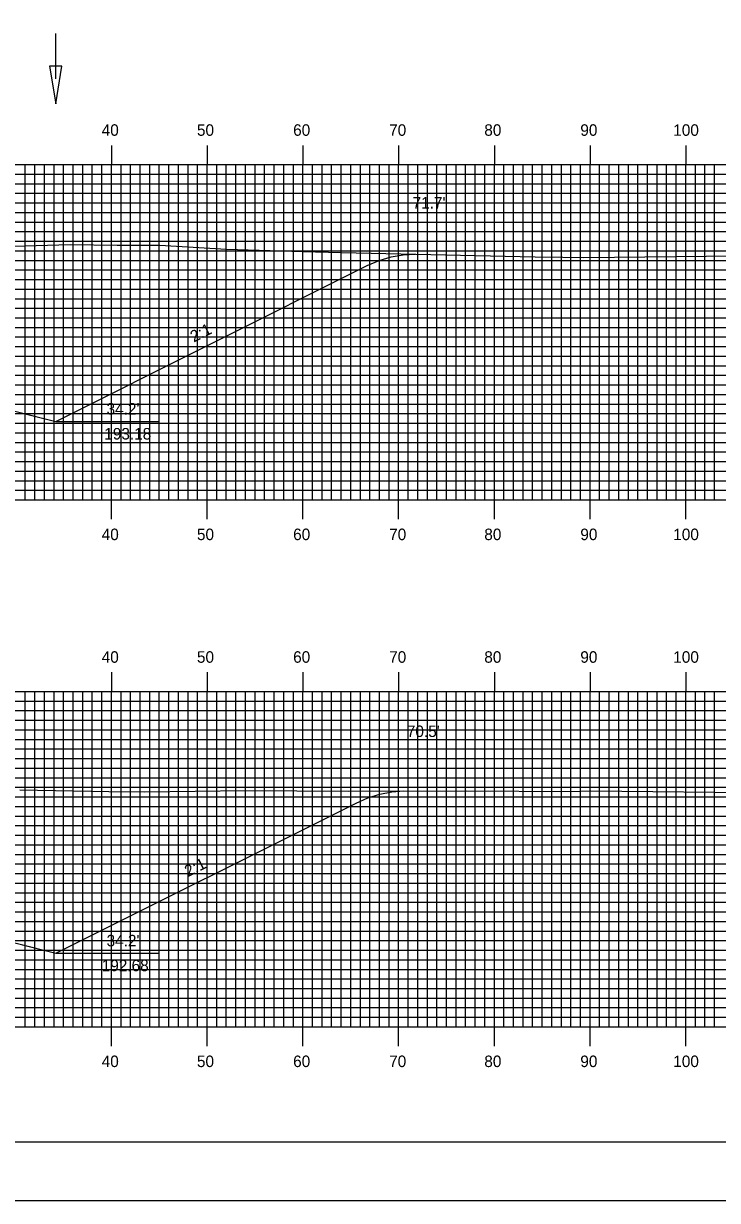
# Model space of a CAD drawing. Extents: x 1799962 to 1800305, y 442591 to 442811.
# Drawn here: x 1800158.3 to 1800230.8, y 442590.5 to 442713.4 of the extents above; entities that cross this region are included whole.
import ezdxf

# ---------------------------------------------------------------- set-up
doc = ezdxf.new("R2010")
doc.units = 0
for name, color, linetype in [('ANNOTATION', 7, 'Continuous'), ('BORDER', 7, 'Continuous'), ('D_Drainage_Ditch_Line', 7, 'Continuous'), ('D_Roadway_Centerline', 7, 'Continuous'), ('D_Roadway_SlopeLines', 7, 'Continuous'), ('D_Text_Standard', 7, 'Continuous'), ('H_V ANNOTATION', 7, 'Continuous'), ('MAJOR', 7, 'Continuous'), ('MINOR', 7, 'Continuous'), ('PDRAIN', 7, 'Continuous'), ('PLOT BOUNDARY', 7, 'Continuous'), ('S_Roadway_Centerline', 7, 'Continuous')]:
    doc.layers.add(name, color=color, linetype=linetype)

msp = doc.modelspace()

# ---------------------------------------------------------------- linework, layer by layer
at = {"layer": 'BORDER'}
msp.add_lwpolyline([(1799977.92, 442596.67), (1800297.92, 442596.67), (1800297.92, 442806.67), (1799977.92, 442806.67)], close=True, dxfattribs=at)
at = {"layer": 'D_Drainage_Ditch_Line'}
msp.add_line((1800161.7, 442707.63), (1800161.7, 442712.33), dxfattribs=at)
msp.add_lwpolyline([(1800162.35, 442708.94), (1800161.04, 442708.94), (1800161.7, 442705)], close=True, dxfattribs=at)
at = {"layer": 'D_Roadway_Centerline'}
for points in [[(1800054.75, 442690.37), (1800056, 442690.29), (1800057.25, 442690.06), (1800058.5, 442689.67), (1800059.75, 442689.13), (1800093.35, 442672.33), (1800097.35, 442673.33), (1800107.52, 442675.87), (1800115.52, 442676.19), (1800127.52, 442675.95), (1800139.52, 442675.71), (1800147.52, 442675.39), (1800157.7, 442672.85), (1800161.7, 442671.85), (1800194.25, 442688.12), (1800195.5, 442688.67), (1800196.75, 442689.05), (1800198, 442689.26), (1800199.25, 442689.32)], [(1800057.29, 442633.58), (1800058.54, 442633.51), (1800059.79, 442633.29), (1800061.04, 442632.9), (1800062.29, 442632.35), (1800093.35, 442616.83), (1800097.35, 442617.83), (1800107.52, 442620.37), (1800115.52, 442620.69), (1800127.52, 442620.45), (1800139.52, 442620.21), (1800147.52, 442619.89), (1800157.7, 442617.35), (1800161.7, 442616.35), (1800193.07, 442632.03), (1800194.32, 442632.58), (1800195.57, 442632.97), (1800196.82, 442633.21), (1800198.07, 442633.29)]]:
    msp.add_lwpolyline(points, dxfattribs=at)
at = {"layer": 'D_Roadway_SlopeLines'}
for points in [[(1800161.7, 442671.85), (1800194.25, 442688.12), (1800195.5, 442688.67), (1800196.75, 442689.05), (1800198, 442689.26), (1800199.25, 442689.32)], [(1800147.52, 442675.39), (1800161.7, 442671.85)], [(1800161.7, 442616.35), (1800193.07, 442632.03), (1800194.32, 442632.58), (1800195.57, 442632.97), (1800196.82, 442633.21), (1800198.07, 442633.29)], [(1800147.52, 442619.89), (1800161.7, 442616.35)]]:
    msp.add_lwpolyline(points, dxfattribs=at)
at = {"layer": 'MAJOR'}
for p, q in [((1800167.52, 442700.67), (1800167.52, 442698.67)), ((1800177.52, 442700.67), (1800177.52, 442698.67)), ((1800187.52, 442700.67), (1800187.52, 442698.67)), ((1800197.52, 442700.67), (1800197.52, 442698.67)), ((1800207.52, 442700.67), (1800207.52, 442698.67)), ((1800217.52, 442700.67), (1800217.52, 442698.67)), ((1800227.52, 442700.67), (1800227.52, 442698.67)), ((1799987.52, 442698.67), (1800267.52, 442698.67)), ((1799987.52, 442698.67), (1800267.52, 442698.67)), ((1800167.52, 442663.67), (1800167.52, 442698.67)), ((1800177.52, 442663.67), (1800177.52, 442698.67)), ((1800187.52, 442663.67), (1800187.52, 442698.67)), ((1800197.52, 442663.67), (1800197.52, 442698.67)), ((1800207.52, 442663.67), (1800207.52, 442698.67)), ((1800217.52, 442663.67), (1800217.52, 442698.67)), ((1800227.52, 442663.67), (1800227.52, 442698.67)), ((1799987.52, 442693.67), (1800267.52, 442693.67)), ((1799987.52, 442688.67), (1800267.52, 442688.67)), ((1799987.52, 442683.67), (1800267.52, 442683.67)), ((1799987.52, 442678.67), (1800267.52, 442678.67)), ((1799987.52, 442673.67), (1800267.52, 442673.67)), ((1799987.52, 442668.67), (1800267.52, 442668.67)), ((1799987.52, 442663.67), (1800267.52, 442663.67)), ((1799987.52, 442663.67), (1800267.52, 442663.67)), ((1800167.52, 442661.66), (1800167.52, 442663.67)), ((1800177.52, 442661.66), (1800177.52, 442663.67)), ((1800187.52, 442661.66), (1800187.52, 442663.67)), ((1800197.52, 442661.66), (1800197.52, 442663.67)), ((1800207.52, 442661.66), (1800207.52, 442663.67)), ((1800217.52, 442661.66), (1800217.52, 442663.67)), ((1800227.52, 442661.66), (1800227.52, 442663.67)), ((1800167.52, 442645.67), (1800167.52, 442643.67)), ((1800177.52, 442645.67), (1800177.52, 442643.67)), ((1800187.52, 442645.67), (1800187.52, 442643.67)), ((1800197.52, 442645.67), (1800197.52, 442643.67)), ((1800207.52, 442645.67), (1800207.52, 442643.67)), ((1800217.52, 442645.67), (1800217.52, 442643.67)), ((1800227.52, 442645.67), (1800227.52, 442643.67)), ((1799987.52, 442643.67), (1800267.52, 442643.67)), ((1799987.52, 442643.67), (1800267.52, 442643.67)), ((1800167.52, 442608.67), (1800167.52, 442643.67)), ((1800177.52, 442608.67), (1800177.52, 442643.67)), ((1800187.52, 442608.67), (1800187.52, 442643.67)), ((1800197.52, 442608.67), (1800197.52, 442643.67)), ((1800207.52, 442608.67), (1800207.52, 442643.67)), ((1800217.52, 442608.67), (1800217.52, 442643.67)), ((1800227.52, 442608.67), (1800227.52, 442643.67)), ((1799987.52, 442638.67), (1800267.52, 442638.67)), ((1799987.52, 442633.67), (1800267.52, 442633.67)), ((1799987.52, 442628.67), (1800267.52, 442628.67)), ((1799987.52, 442623.67), (1800267.52, 442623.67)), ((1799987.52, 442618.67), (1800267.52, 442618.67)), ((1799987.52, 442613.67), (1800267.52, 442613.67)), ((1799987.52, 442608.67), (1800267.52, 442608.67)), ((1799987.52, 442608.67), (1800267.52, 442608.67)), ((1800167.52, 442606.66), (1800167.52, 442608.67)), ((1800177.52, 442606.66), (1800177.52, 442608.67)), ((1800187.52, 442606.66), (1800187.52, 442608.67)), ((1800197.52, 442606.66), (1800197.52, 442608.67)), ((1800207.52, 442606.66), (1800207.52, 442608.67)), ((1800217.52, 442606.66), (1800217.52, 442608.67)), ((1800227.52, 442606.66), (1800227.52, 442608.67))]:
    msp.add_line(p, q, dxfattribs=at)
at = {"layer": 'MINOR'}
for p, q in [((1800158.52, 442663.67), (1800158.52, 442698.67)), ((1800159.52, 442663.67), (1800159.52, 442698.67)), ((1800160.52, 442663.67), (1800160.52, 442698.67)), ((1800161.52, 442663.67), (1800161.52, 442698.67)), ((1800162.52, 442663.67), (1800162.52, 442698.67)), ((1800163.52, 442663.67), (1800163.52, 442698.67)), ((1800164.52, 442663.67), (1800164.52, 442698.67)), ((1800165.52, 442663.67), (1800165.52, 442698.67)), ((1800166.52, 442663.67), (1800166.52, 442698.67)), ((1800168.52, 442663.67), (1800168.52, 442698.67)), ((1800169.52, 442663.67), (1800169.52, 442698.67)), ((1800170.52, 442663.67), (1800170.52, 442698.67)), ((1800171.52, 442663.67), (1800171.52, 442698.67)), ((1800172.52, 442663.67), (1800172.52, 442698.67)), ((1800173.52, 442663.67), (1800173.52, 442698.67)), ((1800174.52, 442663.67), (1800174.52, 442698.67)), ((1800175.52, 442663.67), (1800175.52, 442698.67)), ((1800176.52, 442663.67), (1800176.52, 442698.67)), ((1800178.52, 442663.67), (1800178.52, 442698.67)), ((1800179.52, 442663.67), (1800179.52, 442698.67)), ((1800180.52, 442663.67), (1800180.52, 442698.67)), ((1800181.52, 442663.67), (1800181.52, 442698.67)), ((1800182.52, 442663.67), (1800182.52, 442698.67)), ((1800183.52, 442663.67), (1800183.52, 442698.67)), ((1800184.52, 442663.67), (1800184.52, 442698.67)), ((1800185.52, 442663.67), (1800185.52, 442698.67)), ((1800186.52, 442663.67), (1800186.52, 442698.67)), ((1800188.52, 442663.67), (1800188.52, 442698.67)), ((1800189.52, 442663.67), (1800189.52, 442698.67)), ((1800190.52, 442663.67), (1800190.52, 442698.67)), ((1800191.52, 442663.67), (1800191.52, 442698.67)), ((1800192.52, 442663.67), (1800192.52, 442698.67)), ((1800193.52, 442663.67), (1800193.52, 442698.67)), ((1800194.52, 442663.67), (1800194.52, 442698.67)), ((1800195.52, 442663.67), (1800195.52, 442698.67)), ((1800196.52, 442663.67), (1800196.52, 442698.67)), ((1800198.52, 442663.67), (1800198.52, 442698.67)), ((1800199.52, 442663.67), (1800199.52, 442698.67)), ((1800200.52, 442663.67), (1800200.52, 442698.67)), ((1800201.52, 442663.67), (1800201.52, 442698.67)), ((1800202.52, 442663.67), (1800202.52, 442698.67)), ((1800203.52, 442663.67), (1800203.52, 442698.67)), ((1800204.52, 442663.67), (1800204.52, 442698.67)), ((1800205.52, 442663.67), (1800205.52, 442698.67)), ((1800206.52, 442663.67), (1800206.52, 442698.67)), ((1800208.52, 442663.67), (1800208.52, 442698.67)), ((1800209.52, 442663.67), (1800209.52, 442698.67)), ((1800210.52, 442663.67), (1800210.52, 442698.67)), ((1800211.52, 442663.67), (1800211.52, 442698.67)), ((1800212.52, 442663.67), (1800212.52, 442698.67)), ((1800213.52, 442663.67), (1800213.52, 442698.67)), ((1800214.52, 442663.67), (1800214.52, 442698.67)), ((1800215.52, 442663.67), (1800215.52, 442698.67)), ((1800216.52, 442663.67), (1800216.52, 442698.67)), ((1800218.52, 442663.67), (1800218.52, 442698.67)), ((1800219.52, 442663.67), (1800219.52, 442698.67)), ((1800220.52, 442663.67), (1800220.52, 442698.67)), ((1800221.52, 442663.67), (1800221.52, 442698.67)), ((1800222.52, 442663.67), (1800222.52, 442698.67)), ((1800223.52, 442663.67), (1800223.52, 442698.67)), ((1800224.52, 442663.67), (1800224.52, 442698.67)), ((1800225.52, 442663.67), (1800225.52, 442698.67)), ((1800226.52, 442663.67), (1800226.52, 442698.67)), ((1800228.52, 442663.67), (1800228.52, 442698.67)), ((1800229.52, 442663.67), (1800229.52, 442698.67)), ((1800230.52, 442663.67), (1800230.52, 442698.67)), ((1799987.52, 442697.67), (1800267.52, 442697.67)), ((1799987.52, 442696.67), (1800267.52, 442696.67)), ((1799987.52, 442695.67), (1800267.52, 442695.67)), ((1799987.52, 442694.67), (1800267.52, 442694.67)), ((1799987.52, 442692.67), (1800267.52, 442692.67)), ((1799987.52, 442691.67), (1800267.52, 442691.67)), ((1799987.52, 442690.67), (1800267.52, 442690.67)), ((1799987.52, 442689.67), (1800267.52, 442689.67)), ((1799987.52, 442687.67), (1800267.52, 442687.67)), ((1799987.52, 442686.67), (1800267.52, 442686.67)), ((1799987.52, 442685.67), (1800267.52, 442685.67)), ((1799987.52, 442684.67), (1800267.52, 442684.67)), ((1799987.52, 442682.67), (1800267.52, 442682.67)), ((1799987.52, 442681.67), (1800267.52, 442681.67)), ((1799987.52, 442680.67), (1800267.52, 442680.67)), ((1799987.52, 442679.67), (1800267.52, 442679.67)), ((1799987.52, 442677.67), (1800267.52, 442677.67)), ((1799987.52, 442676.67), (1800267.52, 442676.67)), ((1799987.52, 442675.67), (1800267.52, 442675.67)), ((1799987.52, 442674.67), (1800267.52, 442674.67)), ((1799987.52, 442672.67), (1800267.52, 442672.67)), ((1799987.52, 442671.67), (1800267.52, 442671.67)), ((1799987.52, 442670.67), (1800267.52, 442670.67)), ((1799987.52, 442669.67), (1800267.52, 442669.67)), ((1799987.52, 442667.67), (1800267.52, 442667.67)), ((1799987.52, 442666.67), (1800267.52, 442666.67)), ((1799987.52, 442665.67), (1800267.52, 442665.67)), ((1799987.52, 442664.67), (1800267.52, 442664.67)), ((1800158.52, 442608.67), (1800158.52, 442643.67)), ((1800159.52, 442608.67), (1800159.52, 442643.67)), ((1800160.52, 442608.67), (1800160.52, 442643.67)), ((1800161.52, 442608.67), (1800161.52, 442643.67)), ((1800162.52, 442608.67), (1800162.52, 442643.67)), ((1800163.52, 442608.67), (1800163.52, 442643.67)), ((1800164.52, 442608.67), (1800164.52, 442643.67)), ((1800165.52, 442608.67), (1800165.52, 442643.67)), ((1800166.52, 442608.67), (1800166.52, 442643.67)), ((1800168.52, 442608.67), (1800168.52, 442643.67)), ((1800169.52, 442608.67), (1800169.52, 442643.67)), ((1800170.52, 442608.67), (1800170.52, 442643.67)), ((1800171.52, 442608.67), (1800171.52, 442643.67)), ((1800172.52, 442608.67), (1800172.52, 442643.67)), ((1800173.52, 442608.67), (1800173.52, 442643.67)), ((1800174.52, 442608.67), (1800174.52, 442643.67)), ((1800175.52, 442608.67), (1800175.52, 442643.67)), ((1800176.52, 442608.67), (1800176.52, 442643.67)), ((1800178.52, 442608.67), (1800178.52, 442643.67)), ((1800179.52, 442608.67), (1800179.52, 442643.67)), ((1800180.52, 442608.67), (1800180.52, 442643.67)), ((1800181.52, 442608.67), (1800181.52, 442643.67)), ((1800182.52, 442608.67), (1800182.52, 442643.67)), ((1800183.52, 442608.67), (1800183.52, 442643.67)), ((1800184.52, 442608.67), (1800184.52, 442643.67)), ((1800185.52, 442608.67), (1800185.52, 442643.67)), ((1800186.52, 442608.67), (1800186.52, 442643.67)), ((1800188.52, 442608.67), (1800188.52, 442643.67)), ((1800189.52, 442608.67), (1800189.52, 442643.67)), ((1800190.52, 442608.67), (1800190.52, 442643.67)), ((1800191.52, 442608.67), (1800191.52, 442643.67)), ((1800192.52, 442608.67), (1800192.52, 442643.67)), ((1800193.52, 442608.67), (1800193.52, 442643.67)), ((1800194.52, 442608.67), (1800194.52, 442643.67)), ((1800195.52, 442608.67), (1800195.52, 442643.67)), ((1800196.52, 442608.67), (1800196.52, 442643.67)), ((1800198.52, 442608.67), (1800198.52, 442643.67)), ((1800199.52, 442608.67), (1800199.52, 442643.67)), ((1800200.52, 442608.67), (1800200.52, 442643.67)), ((1800201.52, 442608.67), (1800201.52, 442643.67)), ((1800202.52, 442608.67), (1800202.52, 442643.67)), ((1800203.52, 442608.67), (1800203.52, 442643.67)), ((1800204.52, 442608.67), (1800204.52, 442643.67)), ((1800205.52, 442608.67), (1800205.52, 442643.67)), ((1800206.52, 442608.67), (1800206.52, 442643.67)), ((1800208.52, 442608.67), (1800208.52, 442643.67)), ((1800209.52, 442608.67), (1800209.52, 442643.67)), ((1800210.52, 442608.67), (1800210.52, 442643.67)), ((1800211.52, 442608.67), (1800211.52, 442643.67)), ((1800212.52, 442608.67), (1800212.52, 442643.67)), ((1800213.52, 442608.67), (1800213.52, 442643.67)), ((1800214.52, 442608.67), (1800214.52, 442643.67)), ((1800215.52, 442608.67), (1800215.52, 442643.67)), ((1800216.52, 442608.67), (1800216.52, 442643.67)), ((1800218.52, 442608.67), (1800218.52, 442643.67)), ((1800219.52, 442608.67), (1800219.52, 442643.67)), ((1800220.52, 442608.67), (1800220.52, 442643.67)), ((1800221.52, 442608.67), (1800221.52, 442643.67)), ((1800222.52, 442608.67), (1800222.52, 442643.67)), ((1800223.52, 442608.67), (1800223.52, 442643.67)), ((1800224.52, 442608.67), (1800224.52, 442643.67)), ((1800225.52, 442608.67), (1800225.52, 442643.67)), ((1800226.52, 442608.67), (1800226.52, 442643.67)), ((1800228.52, 442608.67), (1800228.52, 442643.67)), ((1800229.52, 442608.67), (1800229.52, 442643.67)), ((1800230.52, 442608.67), (1800230.52, 442643.67)), ((1799987.52, 442642.67), (1800267.52, 442642.67)), ((1799987.52, 442641.67), (1800267.52, 442641.67)), ((1799987.52, 442640.67), (1800267.52, 442640.67)), ((1799987.52, 442639.67), (1800267.52, 442639.67)), ((1799987.52, 442637.67), (1800267.52, 442637.67)), ((1799987.52, 442636.67), (1800267.52, 442636.67)), ((1799987.52, 442635.67), (1800267.52, 442635.67)), ((1799987.52, 442634.67), (1800267.52, 442634.67)), ((1799987.52, 442632.67), (1800267.52, 442632.67)), ((1799987.52, 442631.67), (1800267.52, 442631.67)), ((1799987.52, 442630.67), (1800267.52, 442630.67)), ((1799987.52, 442629.67), (1800267.52, 442629.67)), ((1799987.52, 442627.67), (1800267.52, 442627.67)), ((1799987.52, 442626.67), (1800267.52, 442626.67)), ((1799987.52, 442625.67), (1800267.52, 442625.67)), ((1799987.52, 442624.67), (1800267.52, 442624.67)), ((1799987.52, 442622.67), (1800267.52, 442622.67)), ((1799987.52, 442621.67), (1800267.52, 442621.67)), ((1799987.52, 442620.67), (1800267.52, 442620.67)), ((1799987.52, 442619.67), (1800267.52, 442619.67)), ((1799987.52, 442617.67), (1800267.52, 442617.67)), ((1799987.52, 442616.67), (1800267.52, 442616.67)), ((1799987.52, 442615.67), (1800267.52, 442615.67)), ((1799987.52, 442614.67), (1800267.52, 442614.67)), ((1799987.52, 442612.67), (1800267.52, 442612.67)), ((1799987.52, 442611.67), (1800267.52, 442611.67)), ((1799987.52, 442610.67), (1800267.52, 442610.67)), ((1799987.52, 442609.67), (1800267.52, 442609.67))]:
    msp.add_line(p, q, dxfattribs=at)
at = {"layer": 'PDRAIN'}
for p, q in [((1800161.7, 442671.85), (1800172.47, 442671.85)), ((1800161.7, 442616.35), (1800172.47, 442616.35))]:
    msp.add_line(p, q, dxfattribs=at)
at = {"layer": 'PLOT BOUNDARY'}
msp.add_lwpolyline([(1799961.74, 442590.55), (1800301.74, 442590.55), (1800301.74, 442810.55), (1799961.74, 442810.55)], close=True, dxfattribs=at)
at = {"layer": 'S_Roadway_Centerline'}
for points in [[(1800144.2, 442689.77), (1800163.19, 442690.31), (1800168.12, 442690.26), (1800172.58, 442690.24), (1800179.53, 442689.82), (1800187.51, 442689.59), (1800191.53, 442689.49), (1800211.8, 442689.03), (1800214.69, 442689), (1800216.87, 442688.95), (1800236.01, 442689.19), (1800240.63, 442689.27), (1800258.56, 442689.3), (1800261.59, 442689.34), (1800267.52, 442689.42)], [(1800157.96, 442633.42), (1800167.23, 442633.22), (1800171.02, 442633.19), (1800181.54, 442633.35), (1800192.26, 442633.27), (1800204.66, 442633.31), (1800215.54, 442633.22), (1800217.61, 442633.3), (1800237.01, 442633.08), (1800241.34, 442632.94), (1800250.84, 442633.25), (1800259.99, 442633.03), (1800267.52, 442632.85)]]:
    msp.add_lwpolyline(points, dxfattribs=at)

# ---------------------------------------------------------------- texts
at = {"layer": 'ANNOTATION'}
for p in [(1800176.12, 442680.09), (1800175.53, 442624.3)]:
    msp.add_text('2:1', height=1.2, rotation=26.5651, dxfattribs=at).set_placement(p)
for s, p in [("34.2'", (1800167.01, 442672.57)), ('193.18', (1800166.77, 442669.97)), ("34.2'", (1800167.01, 442617.07)), ('192.68', (1800166.5, 442614.47))]:
    msp.add_text(s, height=1.2, dxfattribs=at).set_placement(p)
at = {"layer": 'D_Text_Standard'}
for s, p in [("71.7'", (1800198.98, 442694.08)), ("70.5'", (1800198.38, 442638.92))]:
    msp.add_text(s, height=1.2, dxfattribs=at).set_placement(p)
at = {"layer": 'H_V ANNOTATION'}
for s, p in [('40', (1800166.5, 442701.67)), ('50', (1800176.45, 442701.67)), ('60', (1800186.5, 442701.67)), ('70', (1800196.53, 442701.67)), ('80', (1800206.47, 442701.67)), ('90', (1800216.5, 442701.67)), ('100', (1800226.21, 442701.67)), ('40', (1800166.5, 442659.47)), ('50', (1800176.45, 442659.47)), ('60', (1800186.5, 442659.47)), ('70', (1800196.53, 442659.47)), ('80', (1800206.47, 442659.47)), ('90', (1800216.5, 442659.47)), ('100', (1800226.21, 442659.47)), ('40', (1800166.5, 442646.67)), ('50', (1800176.45, 442646.67)), ('60', (1800186.5, 442646.67)), ('70', (1800196.53, 442646.67)), ('80', (1800206.47, 442646.67)), ('90', (1800216.5, 442646.67)), ('100', (1800226.21, 442646.67)), ('40', (1800166.5, 442604.47)), ('50', (1800176.45, 442604.47)), ('60', (1800186.5, 442604.47)), ('70', (1800196.53, 442604.47)), ('80', (1800206.47, 442604.47)), ('90', (1800216.5, 442604.47)), ('100', (1800226.21, 442604.47))]:
    msp.add_text(s, height=1.2, dxfattribs=at).set_placement(p)

doc.saveas('drawing.dxf')
